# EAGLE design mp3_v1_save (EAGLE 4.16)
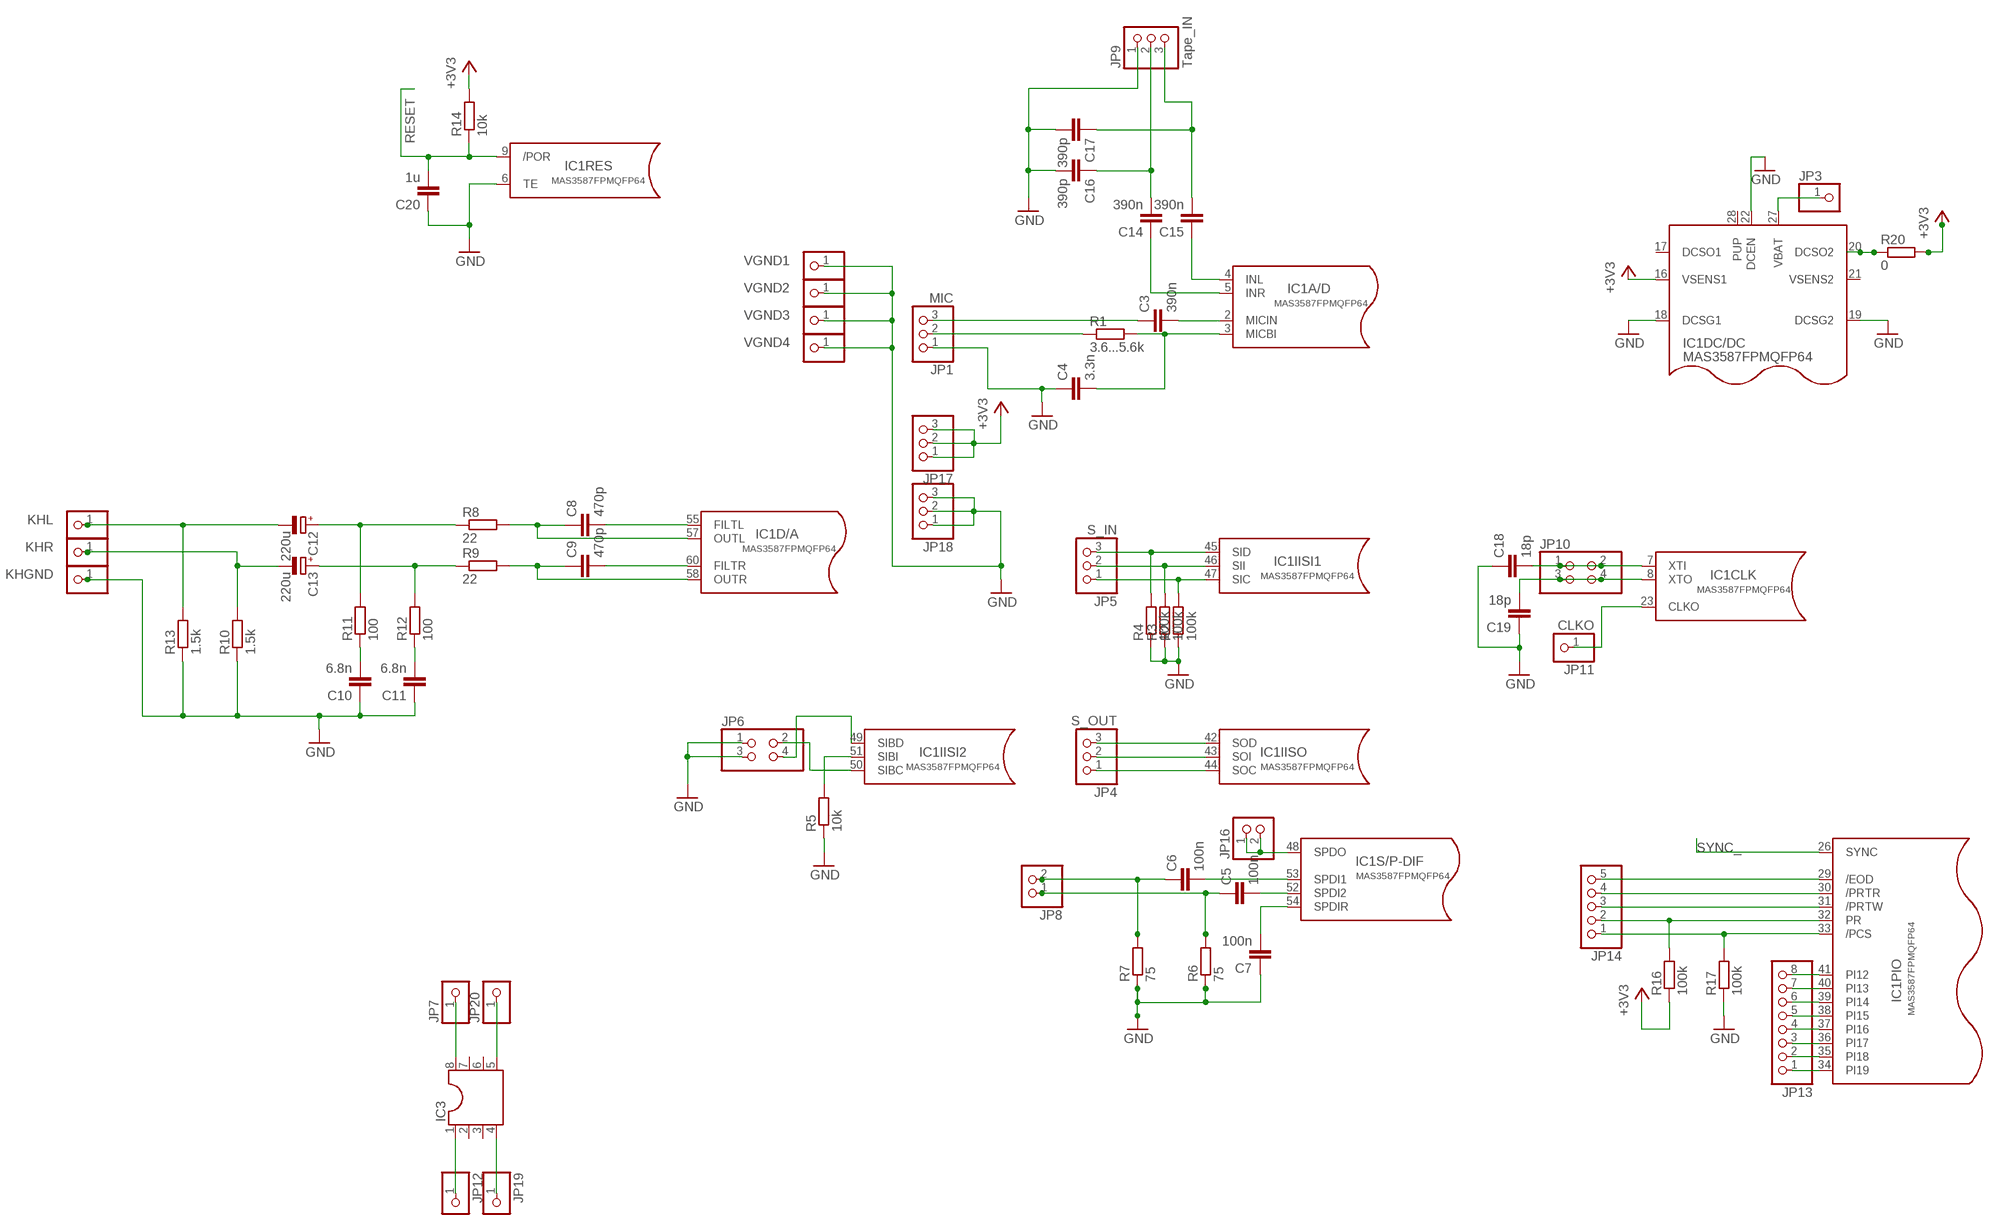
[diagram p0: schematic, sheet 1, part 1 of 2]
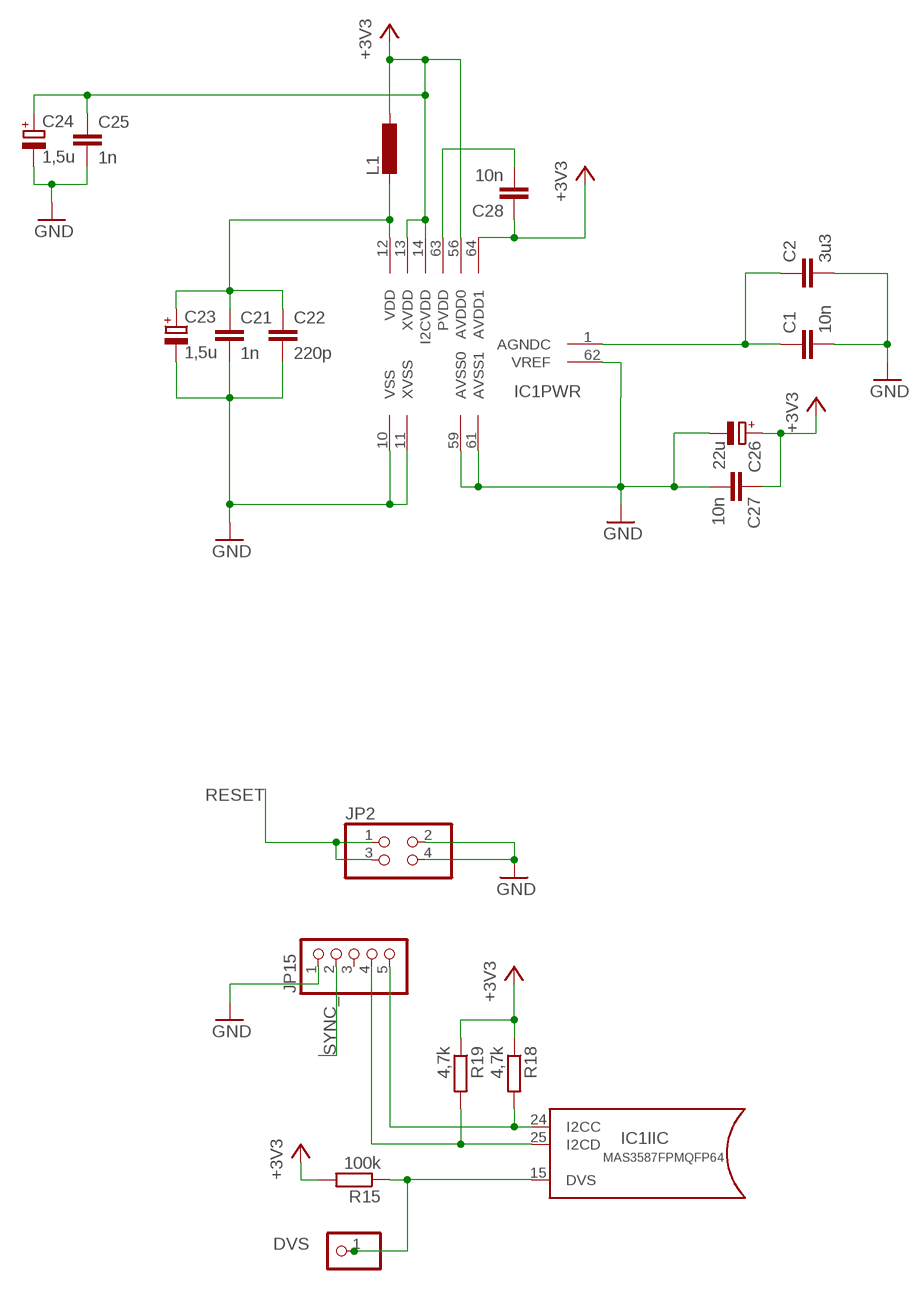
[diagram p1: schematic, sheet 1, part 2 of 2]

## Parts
C1  10n  C5/3.5  [C5B3.5]
C2  3u3  C5/3.5  [C5B3.5]
C3  390n  C5/3.5  [C5B3.5]
C4  3.3n  C5/3.5  [C5B3.5]
C5  100n  C5/3.5  [C5B3.5]
C6  100n  C5/3.5  [C5B3.5]
C7  100n  C5/3.5  [C5B3.5]
C8  470p  C5/3.5  [C5B3.5]
C9  470p  C5/3.5  [C5B3.5]
C10  6.8n  C5/3.5  [C5B3.5]
C11  6.8n  C5/3.5  [C5B3.5]
C12  220u  CPOL-EUE5-8.5  [E5-8,5]
C13  220u  CPOL-EUE5-8.5  [E5-8,5]
C14  390n  C5/3.5  [C5B3.5]
C15  390n  C5/3.5  [C5B3.5]
C16  390p  C5/3.5  [C5B3.5]
C17  390p  C5/3.5  [C5B3.5]
C18  18p  C5/3.5  [C5B3.5]
C19  18p  C5/3.5  [C5B3.5]
C20  1u  C5/3.5  [C5B3.5]
C21  1n  C5/3.5  [C5B3.5]
C22  220p  C5/3.5  [C5B3.5]
C23  1,5u  CPOL-EUE5-8.5  [E5-8,5]
C24  1,5u  CPOL-EUE5-8.5  [E5-8,5]
C25  1n  C5/3.5  [C5B3.5]
C26  22u  CPOL-EUE5-8.5  [E5-8,5]
C27  10n  C5/3.5  [C5B3.5]
C28  10n  C5/3.5  [C5B3.5]
DVS  PINHD-1X1  [1X01]
IC1  MAS3587FPMQFP64  [PMQFP64]
IC3  DIL8S  [SOCKED-08]
JP1  MIC  PINHD-1X3  [1X03]
JP2  PINHD-2X2  [2X02]
JP3  PINHD-1X1  [1X01]
JP4  S_OUT  PINHD-1X3  [1X03]
JP5  S_IN  PINHD-1X3  [1X03]
JP6  PINHD-2X2  [2X02]
JP7  PINHD-1X1  [1X01]
JP8  PINHD-1X2  [1X02]
JP9  Tape_IN  PINHD-1X3  [1X03]
JP10  PINHD-2X2  [2X02]
JP11  CLKO  PINHD-1X1  [1X01]
JP12  PINHD-1X1  [1X01]
JP13  PINHD-1X8  [1X08]
JP14  PINHD-1X5  [1X05]
JP15  PINHD-1X5  [1X05]
JP16  PINHD-1X2  [1X02]
JP17  PINHD-1X3  [1X03]
JP18  PINHD-1X3  [1X03]
JP19  PINHD-1X1  [1X01]
JP20  PINHD-1X1  [1X01]
KHGND  PINHD-1X1  [1X01]
KHL  PINHD-1X1  [1X01]
KHR  PINHD-1X1  [1X01]
L1  L-EU0207/10  [0207/10]
R1  3.6...5.6k  R-EU_0207/10  [0207/10]
R2  100k  R-EU_0207/10  [0207/10]
R3  100k  R-EU_0207/10  [0207/10]
R4  100k  R-EU_0207/10  [0207/10]
R5  10k  R-EU_0207/10  [0207/10]
R6  75  R-EU_0207/10  [0207/10]
R7  75  R-EU_0207/10  [0207/10]
R8  22  R-EU_0207/10  [0207/10]
R9  22  R-EU_0207/10  [0207/10]
R10  1.5k  R-EU_0207/10  [0207/10]
R11  100  R-EU_0207/10  [0207/10]
R12  100  R-EU_0207/10  [0207/10]
R13  1.5k  R-EU_0207/10  [0207/10]
R14  10k  R-EU_0207/10  [0207/10]
R15  100k  R-EU_0207/10  [0207/10]
R16  100k  R-EU_0207/10  [0207/10]
R17  100k  R-EU_0207/10  [0207/10]
R18  4,7k  R-EU_0207/10  [0207/10]
R19  4,7k  R-EU_0207/10  [0207/10]
R20  0  R-EU_0207/5V  [0207/5V]
VGND1  PINHD-1X1  [1X01]
VGND2  PINHD-1X1  [1X01]
VGND3  PINHD-1X1  [1X01]
VGND4  PINHD-1X1  [1X01]

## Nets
+3V3: C24.+ C25.1 C26.+ C27.1 C28.1 IC1.13(PWR:XVDD) IC1.14(PWR:I2CVDD) IC1.16(DC/DC:VSENS1) IC1.56(PWR:AVDD0) IC1.64(PWR:AVDD1) JP17.1 JP17.2 JP17.3 L1.1 R14.2 R15.2 R16.1 R18.1 R19.1 R20.2
GND: C1.2 C2.2 C4.1 C7.1 C10.1 C11.1 C16.2 C17.2 C18.1 C19.1 C20.1 C21.2 C22.2 C23.- C24.- C25.2 C26.- C27.2 IC1.6(RES:TE) IC1.10(PWR:VSS) IC1.11(PWR:XVSS) IC1.18(DC/DC:DCSG1) IC1.19(DC/DC:DCSG2) IC1.22(DC/DC:DCEN) IC1.59(PWR:AVSS0) IC1.61(PWR:AVSS1) IC1.62(PWR:VREF) JP1.1 JP2.2 JP2.4 JP6.1 JP6.3 JP9.1 JP15.1 JP18.1 JP18.2 JP18.3 KHGND.1 R2.1 R3.1 R4.1 R5.1 R6.1 R7.1 R10.1 R13.1 R17.1 VGND1.1 VGND2.1 VGND3.1 VGND4.1
N$1: C1.1 C2.1 IC1.1(PWR:AGNDC)
N$2: C3.1 JP1.3
N$3: C4.2 IC1.3(A/D:MICBI) R1.2
N$4: C15.1 IC1.4(A/D:INL)
N$5: IC1.42(IISO:SOD) JP4.3
N$6: IC1.43(IISO:SOI) JP4.2
N$7: IC1.44(IISO:SOC) JP4.1
N$8: IC1.45(IISI1:SID) JP5.3 R4.2
N$9: IC1.46(IISI1:SII) JP5.2 R3.2
N$10: IC1.47(IISI1:SIC) JP5.1 R2.2
N$11: C5.2 IC1.52(S/P-DIF:SPDI2)
N$12: IC1.50(IISI2:SIBC) JP6.2
N$13: IC1.51(IISI2:SIBI) R5.2
N$14: IC1.49(IISI2:SIBD) JP6.4
N$15: C5.1 JP8.1 R6.2
N$16: C6.2 IC1.53(S/P-DIF:SPDI1)
N$17: C6.1 JP8.2 R7.2
N$18: C7.2 IC1.54(S/P-DIF:SPDIR)
N$19: IC1.27(DC/DC:VBAT) JP3.1
N$20: C8.2 IC1.55(D/A:FILTL)
N$21: C9.2 IC1.60(D/A:FILTR)
N$22: C8.1 IC1.57(D/A:OUTL) R8.2
N$23: C9.1 IC1.58(D/A:OUTR) R9.2
N$24: C12.+ R8.1 R11.2
N$25: C10.2 R11.1
N$26: C11.2 R12.1
N$27: IC3.8 JP7.1
N$28: C13.+ R9.1 R12.2
N$29: JP1.2 R1.1
N$30: C15.2 C17.1 JP9.3
N$31: C14.1 IC1.5(A/D:INR)
N$32: C14.2 C16.1 JP9.2
N$33: C19.2 IC1.8(CLK:XTO) JP10.3 JP10.4
N$34: C18.2 IC1.7(CLK:XTI) JP10.1 JP10.2
N$35: IC1.23(CLK:CLKO) JP11.1
N$36: IC1.48(S/P-DIF:SPDO) JP16.1 JP16.2
N$37: DVS.1 IC1.15(IIC:DVS) R15.1
N$38: IC1.34(PIO:PI19) JP13.1
N$39: IC1.35(PIO:PI18) JP13.2
N$40: IC1.36(PIO:PI17) JP13.3
N$41: IC1.37(PIO:PI16) JP13.4
N$42: IC1.38(PIO:PI15) JP13.5
N$43: IC1.39(PIO:PI14) JP13.6
N$44: IC1.40(PIO:PI13) JP13.7
N$45: IC1.41(PIO:PI12) JP13.8
N$46: IC1.32(PIO:PR) JP14.2 R16.2
N$47: IC1.33(PIO:/PCS) JP14.1 R17.2
N$48: IC1.31(PIO:/PRTW) JP14.3
N$49: IC1.30(PIO:/PRTR) JP14.4
N$50: IC1.29(PIO:/EOD) JP14.5
N$51: IC1.24(IIC:I2CC) JP15.5 R18.2
N$52: IC1.25(IIC:I2CD) JP15.4 R19.2
N$53: C28.2 IC1.63(PWR:PVDD)
N$54: C3.2 IC1.2(A/D:MICIN)
N$55: C21.1 C22.1 C23.+ IC1.12(PWR:VDD) L1.2
N$56: IC3.5 JP20.1
N$57: IC1.20(DC/DC:DCSO2) R20.1
N$58: IC3.1 JP12.1
N$59: IC3.4 JP19.1
N$KHL: C12.- KHL.1 R13.2
N$KHR: C13.- KHR.1 R10.2
RESET: C20.2 IC1.9(RES:/POR) JP2.1 JP2.3 R14.1
SYNC_: IC1.26(PIO:SYNC) JP15.2
Unconnected: IC1.17(DC/DC:DCSO1) IC1.21(DC/DC:VSENS2) IC1.28(DC/DC:PUP) IC3.2 IC3.3 IC3.6 IC3.7 JP15.3

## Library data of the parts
C1-C11 C14-C22 C25 C27 C28 = capacitor-wima:C: CAPACITOR
C12 C13 C23 C24 C26 = rcl:CPOL-EU: POLARIZED CAPACITOR, European symbol
DVS JP3 JP7 JP11 JP12 JP19 JP20 KHGND KHL KHR VGND1-VGND4 = pinhead:PINHD-1X1: PIN HEADER
IC1 = mp3_mas3587:MAS3587F: MAS3587F MPEG Layer 3 Audio Encoder/Decoder Data Sheet Edition Nov. 7, 2001
IC3 = ic-package:DIL8: Dual In Line
JP1 JP4 JP5 JP9 JP17 JP18 = pinhead:PINHD-1X3: PIN HEADER
JP2 JP6 JP10 = pinhead:PINHD-2X2: PIN HEADER
JP8 JP16 = pinhead:PINHD-1X2: PIN HEADER
JP13 = pinhead:PINHD-1X8: PIN HEADER
JP14 JP15 = pinhead:PINHD-1X5: PIN HEADER
L1 = rcl:L-EU: INDUCTOR, European symbol
R1-R20 = rcl:R-EU_: RESISTOR, European symbol

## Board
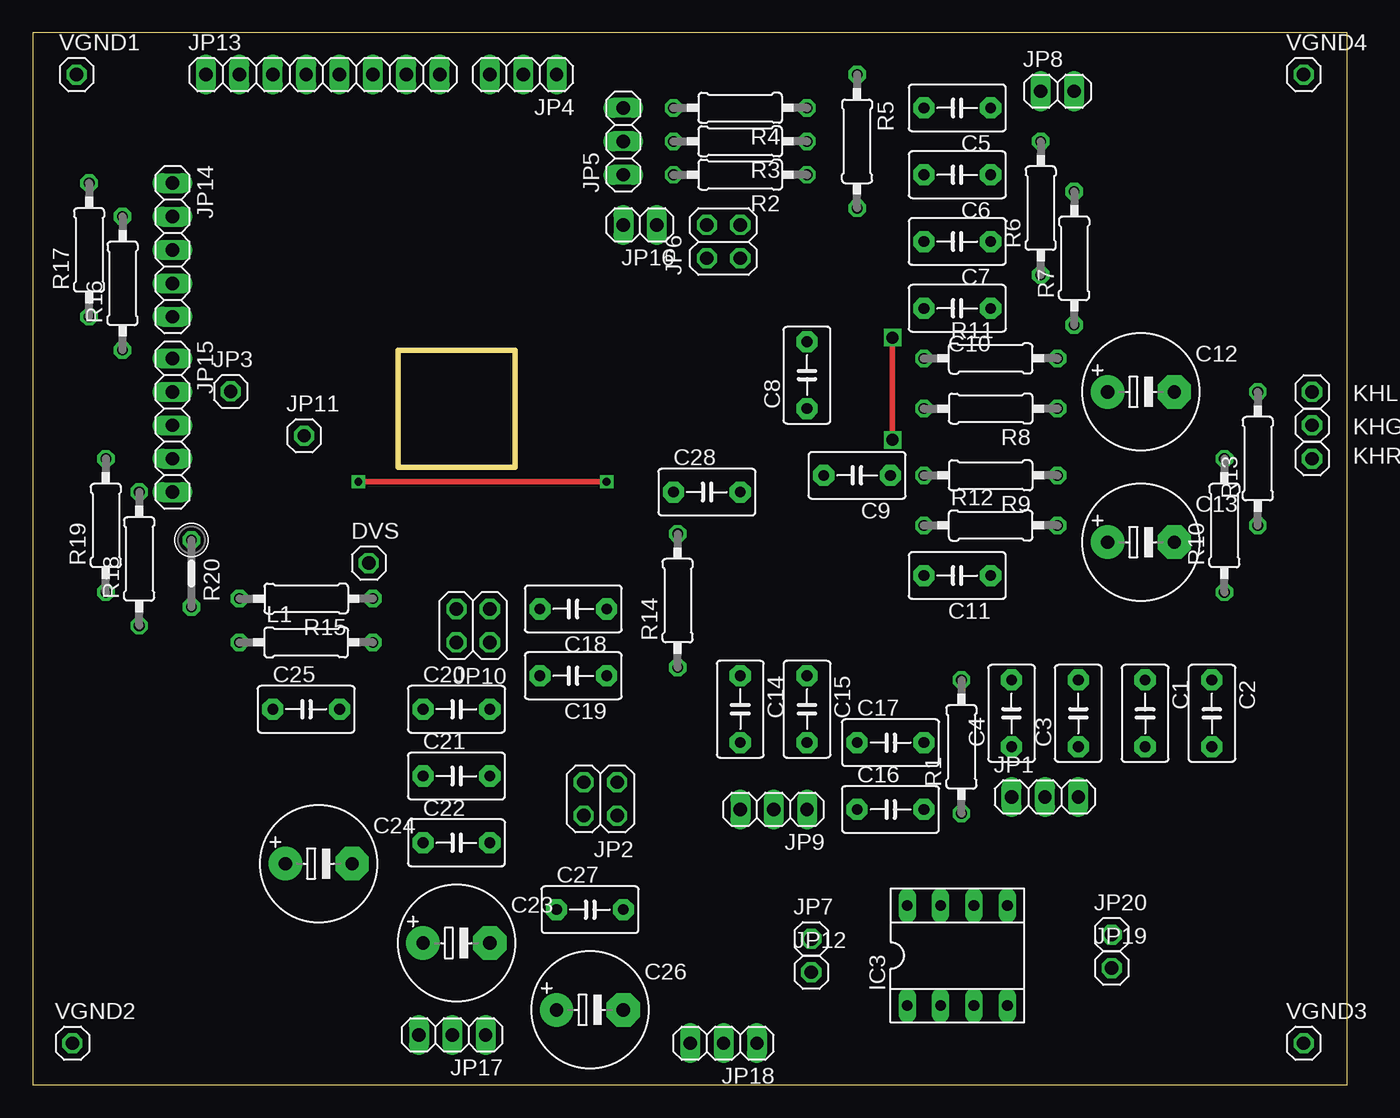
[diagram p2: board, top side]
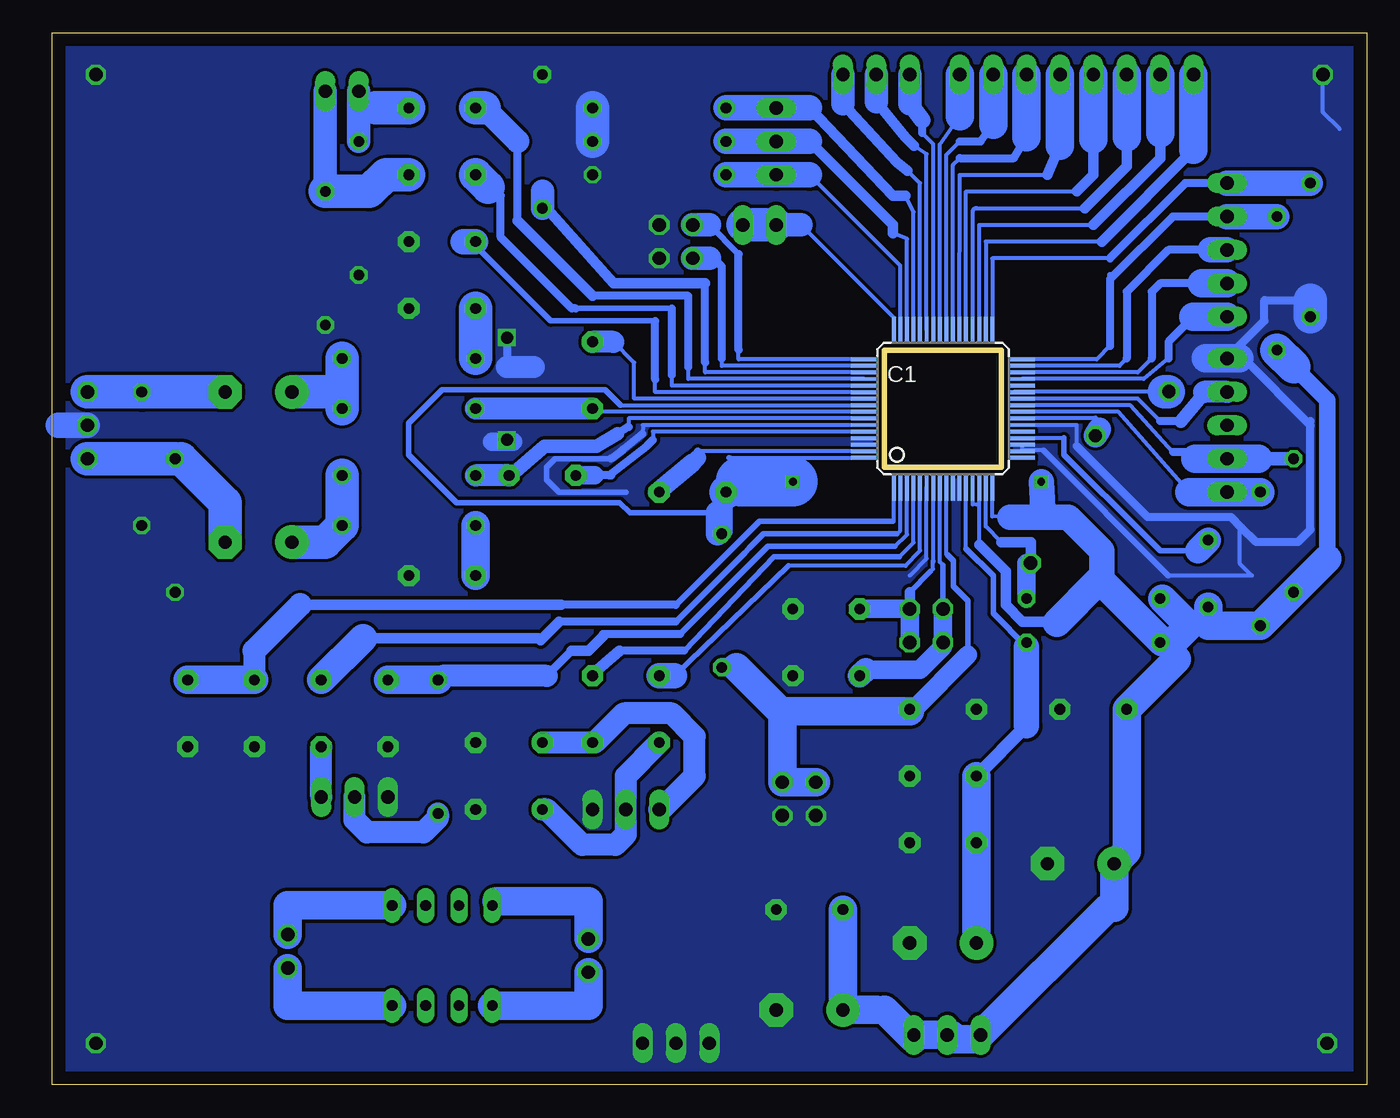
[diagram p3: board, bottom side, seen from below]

Size 100 x 80 mm. Coordinates in mm from the lower left corner, seen from the top.
Outline: 0,0 100,0 100,80 0,80 0,0
Copper layers (1*16): Top 0.035mm / dielectric 1.5mm / Bottom 0.035mm
Design rules "default": minimum track width 10mil, minimum drill 24mil, track to track 8mil, track to pad 8mil, pad to pad 8mil, via to via 8mil, smd to smd 8mil, copper to edge 40mil, drill to drill 8mil, minimum pad ring 10mil, minimum via ring 8mil, stop-mask expansion 4mil, vias tented up to drill 0mil, thermal gap 10mil
bKeepout: area 27.8,47 to 36.7,55.2
bRestrict: area 27.1,46.4 to 37.3,56.5
Milling: area 27.8,47 to 36.7,55.9

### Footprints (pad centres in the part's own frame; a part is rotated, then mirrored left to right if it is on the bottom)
C5B3.5 = drill 0.813 pad 1.6 octagon: 1 -2.54,0; 2 2.54,0
E5-8,5 = drill 1.016 pad 2.54 round: + -2.54,0 | drill 1.016 pad 2.54 octagon: - 2.54,0
1X01 = drill 1.016 octagon: 1 0,0
PMQFP64 = smd 0.3 x 2: 1 -3.75,-6; 2 -3.25,-6; 3 -2.75,-6; 4 -2.25,-6; 5 -1.75,-6; 6 -1.25,-6; 7 -0.75,-6; 8 -0.25,-6; 9 0.25,-6; 10 0.75,-6; 11 1.25,-6; 12 1.75,-6; 13 2.25,-6; 14 2.75,-6; 15 3.25,-6; 16 3.75,-6; 33 3.75,6; 34 3.25,6; 35 2.75,6; 36 2.25,6; 37 1.75,6; 38 1.25,6; 39 0.75,6; 40 0.25,6; 41 -0.25,6; 42 -0.75,6; 43 -1.25,6; 44 -1.75,6; 45 -2.25,6; 46 -2.75,6; 47 -3.25,6; 48 -3.75,6 | smd 2 x 0.3: 17 6,-3.75; 18 6,-3.25; 19 6,-2.75; 20 6,-2.25; 21 6,-1.75; 22 6,-1.25; 23 6,-0.75; 24 6,-0.25; 25 6,0.25; 26 6,0.75; 27 6,1.25; 28 6,1.75; 29 6,2.25; 30 6,2.75; 31 6,3.25; 32 6,3.75; 49 -6,3.75; 50 -6,3.25; 51 -6,2.75; 52 -6,2.25; 53 -6,1.75; 54 -6,1.25; 55 -6,0.75; 56 -6,0.25; 57 -6,-0.25; 58 -6,-0.75; 59 -6,-1.25; 60 -6,-1.75; 61 -6,-2.25; 62 -6,-2.75; 63 -6,-3.25; 64 -6,-3.75
SOCKED-08 = drill 0.813 long: 1 -3.81,-3.81; 2 -1.27,-3.81; 3 1.27,-3.81; 4 3.81,-3.81; 5 3.81,3.81; 6 1.27,3.81; 7 -1.27,3.81; 8 -3.81,3.81
1X03 = drill 1.016 long: 1 -2.54,0; 2 0,0; 3 2.54,0
2X02 = drill 1.016 octagon: 1 -1.27,-1.27; 2 -1.27,1.27; 3 1.27,-1.27; 4 1.27,1.27
1X02 = drill 1.016 long: 1 -1.27,0; 2 1.27,0
1X08 = drill 1.016 long: 1 -8.89,0; 2 -6.35,0; 3 -3.81,0; 4 -1.27,0; 5 1.27,0; 6 3.81,0; 7 6.35,0; 8 8.89,0
1X05 = drill 1.016 long: 1 -5.08,0; 2 -2.54,0; 3 0,0; 4 2.54,0; 5 5.08,0
0207/10 = drill 0.813 octagon: 1 -5.08,0; 2 5.08,0
0207/5V = drill 0.813 octagon: 1 -2.54,0; 2 2.54,0

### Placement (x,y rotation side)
C1  84.61,28.25 270 top
C2  89.69,28.25 270 top
C3  79.53,28.25 90 top
C4  74.45,28.25 90 top
C5  70.32,74.29 180 top
C6  70.32,69.21 180 top
C7  70.32,64.13 180 top
C8  58.89,53.97 90 top
C9  62.7,46.35 180 top
C10  70.32,59.05 180 top
C11  70.32,38.73 180 top
C12  84.29,52.7 0 top
C13  84.29,41.27 0 top
C14  53.81,28.57 270 top
C15  58.89,28.57 270 top
C16  65.24,20.95 0 top
C17  65.24,26.03 0 top
C18  41.11,36.19 180 top
C19  41.11,31.11 180 top
C20  32.22,28.57 0 top
C21  32.22,23.49 0 top
C22  32.22,18.41 0 top
C23  32.22,10.79 0 top
C24  21.74,16.82 0 top
C25  20.79,28.57 0 top
C26  42.38,5.71 0 top
C27  42.38,13.33 0 top
C28  51.27,45.08 0 top
DVS  25.55,39.68 0 top
IC1  32.22,51.43 0 bottom
IC3  70.32,9.84 0 top
JP1  76.99,21.9 0 top
JP2  43.17,21.74 180 top
JP3  15.04,52.73 0 top
JP4  37.3,76.83 180 top
JP5  44.92,71.75 90 top
JP6  52.54,64.13 90 top
JP7  59.21,11.11 0 top
JP8  77.94,75.56 0 top
JP9  56.35,20.95 180 top
JP10  33.49,34.92 180 top
JP11  20.63,49.37 0 top
JP12  59.21,8.57 0 top
JP13  22.06,76.83 0 top
JP14  10.63,63.5 270 top
JP15  10.63,50.16 270 top
JP16  46.19,65.4 180 top
JP17  31.9,3.8 180 top
JP18  52.54,3.17 180 top
JP19  82.07,8.89 0 top
JP20  82.07,11.43 0 top
KHGND  97.31,50.16 0 top
KHL  97.31,52.7 0 top
KHR  97.31,47.62 0 top
L1  20.79,33.65 0 top
R1  70.64,25.71 90 top
R2  53.81,69.21 180 top
R3  53.81,71.75 180 top
R4  53.81,74.29 180 top
R5  62.7,71.75 270 top
R6  76.67,66.67 90 top
R7  79.21,62.86 90 top
R8  72.86,51.43 180 top
R9  72.86,46.35 180 top
R10  90.64,42.54 90 top
R11  72.86,55.24 0 top
R12  72.86,42.54 0 top
R13  93.18,47.62 90 top
R14  49.05,36.83 90 top
R15  20.79,36.98 180 top
R16  6.82,60.96 90 top
R17  4.28,63.5 90 top
R18  8.09,40 90 top
R19  5.55,42.54 90 top
R20  12.06,38.89 270 top
VGND1  3.33,76.83 0 top
VGND2  3.01,3.17 0 top
VGND3  96.67,3.17 0 top
VGND4  96.67,76.83 0 top

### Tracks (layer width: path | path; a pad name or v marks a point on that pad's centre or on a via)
+3V3  (via drill 0.6)
  Top 0.406: v24.76,45.87 v43.65,45.87
  Bottom 0.305: 48.51,47.68 IC1.64 | 56.76,51.68 IC1.56 | IC1.13 29.97,44.16 29.68,44.13 29.47,44.13 | IC1.16 28.47,43.23 27.14,43.18 | 29.36,40.95 29.47,41.06 29.47,44.13 | 29.47,44.13 IC1.14 | 47.78,45.72 47.78,45.4 47.62,45.87
  Bottom 0.406: C28.1 48.73,45.24 | 15.55,33.65 L1.1 15.87,33.81 | R14.2 49.05,41.75 | 56.76,51.68 57.94,52.86 70.32,52.86 72.86,50.32 72.86,47.94 69.21,44.29 56.83,44.29 56.03,43.49 49.37,43.49 | R14.2 | R14.2 | 15.55,36.98 R15.2 | 24.6,43.18 23.01,43.18 | 23.57,35.16 23.65,35.24 | 23.57,35.16 | 20.23,38.33 20.15,38.41 | 48.51,47.68 46.29,46.89 47.46,45.72 47.78,45.72 48.09,45.72 | R14.2 49.37,41.91 | 48.73,42.06 48.89,42.06 R14.2 | R20.2
  Bottom 0.61: 20.23,38.33 20.31,38.41 | 23.57,35.16 23.65,35.08
  Bottom 0.813: 23.65,35.24 26.19,35.24 27.46,36.51 27.46,39.05 29.47,41.06 | JP17.3 29.68,3.49 | 19.68,13.49 19.2,13.49 | JP17.2 32.22,3.8 31.9,3.49 31.27,3.49 31.58,3.8 | JP17.1 34.44,3.49 | 36.66,5.71 37.3,5.71
  Bottom 1.016: L1.1 14.44,32.38 14.44,33.97 | C28.1 48.73,42.06 | 13.49,34.92 12.06,34.92
  Bottom 1.27: 5.55,54.61 3.01,52.07 3.01,40
  Bottom 1.778: 49.37,41.91 49.37,43.49
  Bottom 1.93: 24.6,43.18 v24.76,45.87 | 24.6,43.18 22.7,43.18 20.15,40.64 20.15,38.41 | 24.6,43.18 27.14,43.18
  Bottom 2.184: 3.01,40 R19.1 R18.1 12.06,34.92 R20.2 | C27.1 C26.+ 37.3,5.71 | 15.55,33.65 20.23,38.33 | 14.44,32.38 C25.1 18.25,17.77 C24.+ 19.2,13.49 | 15.55,36.98 13.49,34.92 14.44,33.97 | 20.31,38.41 23.57,35.16 | JP17.3 19.68,13.49 | 29.68,3.49 31.27,3.49 | 34.44,3.49 36.66,5.71 | 31.58,3.8 JP17.1
  Bottom 2.54: 48.09,45.72 C28.1 | 5.55,54.61 R16.1
  Bottom 3.81: v43.65,45.87 47.62,45.87
GND  (via drill 0.9 pad 1.27)
  Top 0.406: v65.4,49.05 v65.4,56.83
  Bottom 0.305: IC1.22 22.06,50.18 22.06,48.57 | v65.4,49.05 66.51,48.89 | 24.6,48.26 26.14,48.26 IC1.18 26.19,48.21 26.19,48.65 IC1.19 | 15.08,38.73 8.73,38.73 9.68,39.68 9.68,42.22 9.52,42.38 | VGND1.1 3.33,73.97 2.06,72.7 | IC1.6 33.47,40.02 34.76,38.73 | IC1.59 55.06,50.18 55.09,49.51
  Bottom 0.406: R17.1 3.96,58.41 | 57.49,47.62 61.75,47.62 62.38,46.98 62.38,46.03 61.43,45.08 56.35,45.08 | 15.08,38.73 24.6,48.26
  Bottom 0.61: 22.06,48.57 16.66,43.18 10.31,43.18 9.52,42.38 8.41,41.27 5.23,41.27 4.28,42.22 4.28,50.16 | 4.28,50.16 4.28,50.48 | v65.4,56.83 65.4,54.61 | 4.28,59.69 7.77,59.69 7.77,58.1 JP15.1 | 9.68,55.24 9.36,55.24 4.28,50.16 | 55.09,49.51 56.7,48.22 56.57,48.32 57.49,47.62
  Bottom 1.422: 66.51,48.89 64.92,48.89
  Bottom 1.676: 65.4,54.61 63.34,54.61
  Bottom 1.93: KHGND.1 99.53,50.16
  Bottom 2.184: 12.22,55.24 JP15.1 9.68,55.24
  Bottom 2.54: R3.1 R4.1 | 4.28,59.69 R17.1
  pour Bottom (isolate 0.254, no thermals): 0.47,79.37 0.47,0.63 99.53,0.63 99.53,79.37
N$1
  Bottom 0.305: IC1.1 35.97,42.92 36.03,42.86
  Bottom 0.406: 36.03,42.86 46.19,42.86 48.57,40.48 | 48.57,40.48 | 48.57,40.48 52.54,36.51
  Bottom 0.61: 52.54,36.51 61.27,36.51
  Bottom 0.813: 61.27,36.51 81.11,36.51
  Bottom 1.676: 84.61,33.02 C1.1
  Bottom 1.778: 81.11,36.51 84.61,33.02
  Bottom 2.184: C1.1 C2.1
N$2
  Bottom 0.406: C3.1 79.37,25.87
  Bottom 1.676: JP1.3 C3.1
N$3
  Bottom 0.305: IC1.3 34.97,41.85 35.87,40.95 | 70.95,30.47 R1.2 70.32,31.11
  Bottom 0.406: 35.87,40.95 45.55,40.95 52.22,34.29 | 58.1,34.29 58.1,34.13
  Bottom 0.61: 52.22,34.29 58.1,34.29 | 60.48,33.02 62.38,31.11
  Bottom 0.813: 58.1,34.13 59.21,33.02 60.48,33.02
  Bottom 1.676: 62.38,31.11 70.32,31.11
  Bottom 2.184: R1.2 C4.2
N$4
  Bottom 0.305: IC1.4 34.47,41.24 35.55,40.16
  Bottom 0.406: 35.55,40.16 45.08,40.16 51.91,33.02 | 59.05,31.11 C15.1
  Bottom 0.61: 51.91,33.02 56.83,33.02
  Bottom 0.813: 56.83,33.02 59.05,31.11
N$5
  Bottom 0.305: IC1.42 32.97,71.55 33.81,72.38
  Bottom 0.61: 33.81,72.38 33.81,73.34
  Bottom 1.27: 33.81,73.34 34.76,74.61
  Bottom 1.778: 34.76,74.61 JP4.3
N$6
  Bottom 0.305: IC1.43 33.47,70.78 34.44,71.43
  Bottom 0.813: 34.44,71.43 35.08,72.07 37.3,74.77
  Bottom 1.778: 37.3,74.77 JP4.2
N$7
  Bottom 0.305: IC1.44 33.97,68.58 34.92,69.53
  Bottom 0.813: 34.92,69.53 35.71,70.16 39.84,74.61
  Bottom 1.778: 39.84,74.61 JP4.1
N$8
  Bottom 0.305: IC1.45 34.47,66.38 35.08,67.62
  Bottom 0.813: 35.08,67.62 36.03,67.62 42.38,74.29
  Bottom 1.93: 42.38,74.29 JP5.3 R4.2
N$9
  Bottom 0.305: IC1.46 34.97,64.34 36.03,64.77
  Bottom 0.813: 36.03,64.77 36.03,65.4 42.38,71.75
  Bottom 1.93: 42.38,71.75 JP5.2 R3.2
N$10
  Bottom 0.305: IC1.47 35.47,62.3 42.38,69.21
  Bottom 1.93: 42.38,69.21 JP5.1 R2.2
N$11
  Bottom 0.305: IC1.52 51.59,53.68 51.59,54.61
  Bottom 0.61: 51.59,54.61 51.59,60 58.89,60 | 64.61,65.72 64.61,71.75
  Bottom 0.813: 58.89,60 64.61,65.72
  Bottom 1.778: 64.61,71.75 67.14,74.29
  Bottom 2.54: 67.14,74.29 C5.2
N$12
  Bottom 0.305: IC1.50 49.05,54.68 49.05,55.24
  Bottom 0.61: 50,62.86 50,63.18 49.05,62.23 49.05,55.24
  Bottom 1.778: 50,62.86 JP6.2
N$13
  Bottom 0.305: IC1.51 50.32,54.18 50.32,54.92
  Bottom 0.61: 50.32,54.92 50.32,60.96
  Bottom 0.813: 50.32,60.96 57.3,60.96 62.7,66.99
  Bottom 1.778: 62.7,67.94 62.7,66.99 R5.2
N$14
  Bottom 0.305: IC1.49 47.78,55.18 47.78,55.88
  Bottom 0.406: 47.78,63.18 50,65.4
  Bottom 0.61: 47.78,55.88 47.78,63.18
  Bottom 1.778: 50,65.4 JP6.4
N$15
  Bottom 0.813: 75.4,74.29 JP8.1
  Bottom 1.778: JP8.1 R6.2
  Bottom 2.54: C5.1 75.4,74.29
N$16
  Bottom 0.305: IC1.53 52.86,53.18 52.86,53.97
  Bottom 0.406: 52.86,59.05 60.16,59.05
  Bottom 0.61: 52.86,53.97 52.86,59.05 | 60.16,59.05 60.48,59.05 65.88,64.45 65.88,67.62 66.51,68.26 66.83,68.26
  Bottom 2.54: 66.83,68.26 C6.2
N$17
  Bottom 1.778: R7.2 JP8.2
  Bottom 2.54: C6.1 74.61,69.21 75.88,67.94 R7.2
N$18
  Bottom 0.305: IC1.54 54.13,52.68 54.13,53.65
  Bottom 0.406: 54.13,58.1 62.06,58.1 68.1,64.13 68.73,64.13
  Bottom 0.61: 54.13,53.65 54.13,58.1
  Bottom 1.93: 68.73,64.13 C7.2
N$19
  Bottom 0.305: JP3.1 15.08,52.7 | 15.39,52.7 26.19,52.7 | 26.19,52.7 26.2,52.7 IC1.27 | 26.19,52.7 26.82,52.7
  Bottom 2.54: 15.08,52.7 15.39,52.7
N$20
  Bottom 0.305: IC1.55 55.71,52.18 55.71,54.92 57.3,56.51
  Bottom 1.676: 57.3,56.51 C8.2
N$21
  Bottom 0.305: IC1.60 54.29,49.68 54.29,49.05
  Bottom 0.61: 57.62,46.35 58.73,46.35 | 57.62,46.35 57.46,46.35 | 54.29,49.05 54.76,48.57 57.62,46.35
  Bottom 1.422: 58.73,46.35 C9.2
N$22
  Bottom 0.305: IC1.57 58.8,51.18
  Bottom 0.406: 58.89,51.27 58.89,51.18 | 58.89,51.27 C8.1 | 58.8,51.18 58.89,51.27
  Bottom 1.676: C8.1 R8.2
N$23
  Bottom 0.305: IC1.58 56.15,50.68 56.15,50.05
  Bottom 0.406: 65.08,46.35 C9.1
  Bottom 0.61: 56.15,50.05 56.98,49.53
  Bottom 1.016: 65.08,46.35 62.54,48.57 58.57,48.57 56.98,49.53
  Bottom 1.676: C9.1 R9.2
N$24
  Bottom 0.406: R8.1 79.21,52.7
  Bottom 2.54: 79.21,52.7 C12.+ | R8.1 R11.2
N$25
  Bottom 0.406: C10.2 67.78,59.21
  Bottom 2.54: R11.1 C10.2
N$26
  Bottom 2.184: C11.2 R12.1
N$27
  Bottom 1.27: 66.19,13.97 IC3.8 | JP7.1 59.21,10.79
  Bottom 2.184: 66.19,13.97 59.21,13.97 JP7.1
N$28
  Bottom 0.406: R9.1 | R9.1 77.78,46.51
  Bottom 2.54: C13.+ 79.21,41.27 R12.2 R9.1
N$29
  Bottom 0.406: JP1.2 76.99,22.06
  Bottom 1.676: R1.1 70.64,20.31 71.75,19.2 76.03,19.2 76.99,20.16 JP1.2
N$30
  Bottom 0.406: 59.05,26.03 58.89,25.87 C15.2 58.73,26.03
  Bottom 1.676: 59.05,26.03 C17.1 | 58.73,26.03 56.51,28.25 52.86,28.25 51.11,26.51 51.11,23.49 53.65,20.95 JP9.3
N$31
  Bottom 0.305: IC1.5 33.97,40.63 35.08,39.46 43.97,39.46
  Bottom 0.406: 43.97,39.46 52.63,31.11
  Bottom 1.93: 52.63,31.11 C14.1
N$32
  Bottom 0.406: JP9.2 56.19,20.95 56.35,20.79
  Bottom 1.676: C16.1 62.38,20.95 59.68,18.25 57.14,18.25 56.35,19.04 56.35,20.79 | JP9.2 56.35,23.49 C14.2
N$33
  Bottom 0.305: 32.47,39.77 IC1.8 | 32.47,39.77 | 32.22,39.52 32.47,39.77
  Bottom 0.406: JP10.3 32.06,36.19 32.22,36.35 32.22,39.52 | 32.22,33.33 JP10.4
  Bottom 1.422: JP10.4 JP10.3 | 32.22,33.33 33.97,31.59 38.09,31.59
  Bottom 1.778: 38.09,31.59 C19.2
N$34
  Bottom 0.305: 32.97,39.91 32.97,39.73 | 32.97,39.91 IC1.7 | 32.97,39.91 32.98,39.91 32.98,39.24 33.17,39.05
  Bottom 0.406: JP10.1 34.6,36.19 | 34.76,37.46 33.17,39.05
  Bottom 0.813: 34.6,36.19 34.76,36.35 34.76,37.46
  Bottom 1.422: C18.2 JP10.1 JP10.2
N$35
  Bottom 0.305: 20.63,50.68 IC1.23
  Bottom 0.406: JP11.1 20.63,50.68
  Bottom 1.778: JP11.1 20.31,49.84
N$36
  Bottom 0.305: IC1.48 35.97,58.36 43.02,65.4
  Bottom 1.778: 43.02,65.4 JP16.2
  Bottom 2.54: JP16.2 JP16.1
N$37
  Bottom 0.305: IC1.15 28.97,42.47 27.77,41.27 | DVS.1 25.87,39.68
  Bottom 0.813: DVS.1 25.55,41.27 27.77,41.27
  Bottom 1.422: 25.87,39.68 R15.1
N$38
  Bottom 0.305: IC1.34 28.97,64.13 20.15,64.13
  Bottom 0.813: 20.15,64.13 13.17,71.11
  Bottom 2.184: 13.17,71.11 JP13.1
N$39
  Bottom 0.305: IC1.35 29.47,65.4 20.79,65.4
  Bottom 0.813: 20.79,65.4 15.71,70.48 15.71,72.38
  Bottom 2.184: 15.71,72.38 JP13.2
N$40
  Bottom 0.305: IC1.36 29.97,66.38 arc90 29.68,66.67 21.42,66.67
  Bottom 0.813: 21.42,66.67 18.25,69.84 18.25,72.07
  Bottom 2.184: 18.25,72.07 JP13.3
N$41
  Bottom 0.305: IC1.37 30.47,67.94 22.06,67.94
  Bottom 0.406: 20.79,71.91 20.79,69.84
  Bottom 0.813: 22.06,67.94 20.79,69.21 20.79,71.91
  Bottom 2.184: 20.79,71.91 JP13.4
N$42
  Bottom 0.305: IC1.38 30.95,69.21 24.28,69.21
  Bottom 0.813: 24.28,69.21 23.33,71.43
  Bottom 2.184: 23.33,71.43 JP13.5
N$43
  Bottom 0.305: IC1.39 31.47,69.96 30.95,70.48
  Bottom 0.61: 30.95,70.48 26.82,70.48 25.87,72.07
  Bottom 2.184: 25.87,72.07 JP13.6
N$44
  Bottom 0.305: IC1.40 31.97,70.73 30.95,71.75
  Bottom 0.61: 30.95,71.75 29.36,71.75 28.41,73.02
  Bottom 2.184: 28.41,73.02 JP13.7
N$45
  Bottom 0.305: IC1.41 32.47,71.5 30.95,73.66
  Bottom 2.184: 30.95,73.66 JP13.8
N$46
  Bottom 0.305: IC1.32 20.53,55.18 19.52,56.19
  Bottom 0.406: JP14.2 11.9,66.03 | 19.52,61.27 19.52,61.59
  Bottom 0.61: 19.52,56.19 19.52,61.27 14.76,66.03 11.9,66.03
  Bottom 1.93: R16.2 JP14.2
N$47
  Bottom 0.305: IC1.33 28.47,62.86 19.52,62.86
  Bottom 0.61: JP14.1 13.81,68.57 19.52,62.86
  Bottom 1.93: R17.2 JP14.1
N$48
  Bottom 0.305: IC1.31 18.81,54.68 18.25,55.24
  Bottom 0.61: 18.25,55.24 18.25,60.32 15.08,63.5 11.27,63.5
  Bottom 1.93: JP14.3 11.27,63.5 11.9,63.5
N$49
  Bottom 0.305: IC1.30 17.4,54.18 16.34,55.24
  Bottom 0.61: 16.34,55.24 16.34,60.32 15.71,60.96 12.54,60.96
  Bottom 2.184: JP14.4 12.54,60.96
N$50
  Bottom 0.305: IC1.29 16.95,53.68 15.08,55.24
  Bottom 0.61: 15.08,55.24 15.08,56.51 13.17,58.41
  Bottom 2.184: JP14.5 13.17,58.41
N$51
  Bottom 0.305: IC1.24 18.88,51.18 13.49,45.08
  Bottom 0.406: JP15.5 10.47,45.08 10.47,44.92
  Bottom 2.184: 13.49,45.08 JP15.5 R18.2
N$52
  Bottom 0.305: IC1.25 17.96,51.68 14.73,48.13 | 13.04,47.62 13.55,48.13 | JP15.4 10.63,47.59 10.66,47.56 10.73,47.62
  Bottom 0.61: 13.55,48.13 14.73,48.13
  Bottom 1.016: R19.2 8.25,47.62
  Bottom 2.184: 8.25,47.62 JP15.4 | 10.73,47.62 13.04,47.62
N$53
  Bottom 0.305: IC1.63 50.87,48.18
  Bottom 0.406: 53.97,45.08 C28.2
  Bottom 0.61: 50.87,48.18 50.87,47.7
  Bottom 1.27: 50.87,47.7 51.27,47.3
  Bottom 1.422: 51.27,47.3 53.97,45.08
N$54
  Bottom 0.305: IC1.2 35.47,42.15 35.71,41.91
  Bottom 0.406: 35.71,41.91 45.87,41.91 46.98,40.79 47.3,40.48 52.54,35.24 | C3.2 79.69,30.79
  Bottom 0.61: 52.54,35.24 61.43,35.24
  Bottom 0.813: 61.43,35.24 62.86,33.81 63.02,33.97 | 63.02,33.97 | 63.02,33.97 76.35,33.97
  Bottom 2.184: 76.35,33.97 C3.2
N$55
  Bottom 0.305: 30.47,40.79 IC1.12
  Bottom 0.406: 29.68,23.65 C21.1 C22.1 29.68,18.25 | 30.47,40.79 28.41,38.73 28.41,35.87 25.87,33.33
  Bottom 1.016: 25.87,33.33 L1.2 | C21.1 25.87,27.3
  Bottom 1.93: 25.87,27.3 25.87,33.33
  Bottom 2.184: C23.+ 29.68,18.25 C21.1
N$56
  Bottom 2.184: JP20.1 82.07,13.65 IC3.5
N$57
  Bottom 0.254: IC1.20 26.19,49.18 26.19,49.21
  Bottom 0.305: 23.04,49.18 26.19,49.18
  Bottom 0.406: 23.04,49.18 23.01,49.21 23.01,47.94 16.82,41.75 16.19,41.11 15.71,40.64 12.85,40.64 | R20.1
  Bottom 0.61: R20.1
  Bottom 1.93: 12.85,40.64 R20.1
N$58
  Bottom 2.184: JP12.1 59.21,6.03 IC3.1
N$59
  Bottom 1.27: 73.81,6.03 IC3.4
  Bottom 2.184: JP19.1 82.07,6.03 IC3.4
N$KHL
  Bottom 0.406: R13.2 93.18,52.86
  Bottom 2.54: C12.- R13.2 KHL.1
N$KHR
  Bottom 0.406: 90.16,47.62 R10.2
  Bottom 2.54: 90.16,47.62 86.83,44.29 C13.- | R10.2 KHR.1
RESET
  Bottom 0.305: IC1.9 31.97,40.39 31.74,40.16
  Bottom 0.406: 31.9,40.32 31.74,40.16 31.43,39.84 31.43,37.94 30.31,36.83 30.31,32.7 | 44.44,28.41 44.6,28.41 | 34.76,28.41 34.6,28.57 C20.2 34.44,28.57
  Bottom 1.422: 47.94,31.74 R14.1 | 30.31,32.7 34.44,28.57
  Bottom 2.184: 44.6,28.41 47.94,31.74 | 34.76,28.41 44.44,28.41 JP2.1 JP2.3
SYNC_
  Bottom 0.305: IC1.26 17.41,52.18 15.71,50.48 | 12.69,52.38 12.54,52.38
  Bottom 0.406: 12.38,52.7 12.69,52.38 12.69,52.18
  Bottom 0.61: 14.12,50.48 15.71,50.48
  Bottom 1.016: 12.54,52.38 14.12,50.48
  Bottom 1.676: JP15.2 12.38,52.7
